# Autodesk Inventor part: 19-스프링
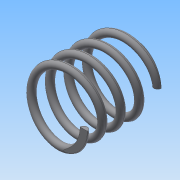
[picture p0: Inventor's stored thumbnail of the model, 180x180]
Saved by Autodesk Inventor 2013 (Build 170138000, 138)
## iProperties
Created: 2017-07
Part Number: 19-스프링
Material: 일반
Document SubType Name: Modeling
Designer: Administrator
Density: 1 g/cm^3
Mass: 0.658108 g
Surface Area: 13.3836 cm^2
Volume: 0.658108 cm^3
Author: Administrator
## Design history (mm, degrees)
sketch "스케치1"
  geometry: L1 (0, 0)-(0, 20.5); L2 (0, 0)-(8.5, 0); L3 (0, 20.5)-(8.5, 20.5); C1 r 1 at (8.5, 0)
  constraints: 6 end point, 1 centre point, 1 coincident, 1 parallel, 1 perpendicular, 1 vertical
  dimensions: "d0" = 20.5 distance of L1.start L1.end (derived); "d1" = 8.5 distance of L1.start L2.end; "d2" = 2 diameter of C1; "d3" = 8.5 distance of L1.end L3.end
feature "코일1" sketch "스케치1" pitch "d4" = 10; turns "d6" = 4; dims "d5" = 20.5 (= d0), "d7" = 0, angle "d8" = 90 deg, angle "d9" = 90 deg, "d10" = 0, "d11" = 0
sketch "스케치2"
  geometry: L1 (20.5, 15)-(0, 15); L2 (0, 15)-(0, -15); L3 (0, -15)-(20.5, -15); L4 (20.5, -15)-(20.5, 15); 2 further points
  constraints: 8 end point, 2 parallel, 1 coincident, 1 horizontal, 1 midpoint, 1 perpendicular
  dimensions: "d12" = 20.5 distance of L1.start L1.end (derived); "d14" = 30 distance of L3.end L1.start
extrude "돌출1" sketch "스케치2" stored distance "d15" = 10; taper "d16" = 0 deg
node "솔리드1"
